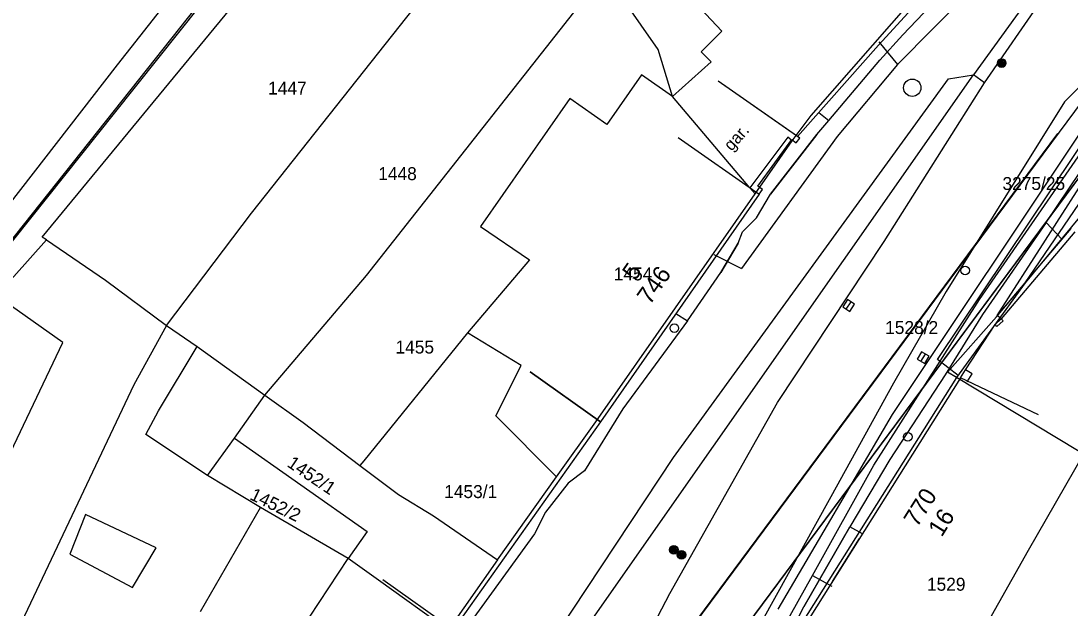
# Model space of a CAD drawing. Extents: x -601580 to 4, y -1204314 to 4.
# Drawn here: x -600374.2 to -600313.5, y -1203904.6 to -1203870.6 of the extents above; entities that cross this region are included whole.
import ezdxf

# ---------------------------------------------------------------- set-up
doc = ezdxf.new("R2010")
doc.units = 0
for name, color, linetype in [('00-INNOGY-NTL', 7, 'Continuous'), ('00-KN-HRANICE PARCEL', 7, 'Continuous'), ('00-KN-PARC. CISLA', 7, 'Continuous'), ('00-KN-VNITRNI KRESBA', 7, 'Continuous'), ('00-POLOHOPIS', 7, 'Continuous'), ('00-RAZÍTKO', 7, 'Continuous'), ('00-SITE KOM. KABEL', 7, 'Continuous'), ('00-VAK-KANAL-POTRUBI', 7, 'Continuous'), ('00-VAK-VODA-RAD IGIS', 7, 'Continuous'), ('Vrstva 25', 7, 'Continuous'), ('Vrstva 27', 7, 'Continuous'), ('Vrstva 28', 7, 'Continuous')]:
    doc.layers.add(name, color=color, linetype=linetype)

# ---------------------------------------------------------------- blocks, each defined once
blk = doc.blocks.new('6.01A_950')
at = {"layer": 'Vrstva 25'}
for radius in [0.25, 0.2, 0.15, 0.1, 0.05]:
    blk.add_circle((0, 0), radius, dxfattribs=at)
blk = doc.blocks.new('6.01A_952')
at = {"layer": 'Vrstva 25'}
for radius in [0.25, 0.2, 0.15, 0.1, 0.05]:
    blk.add_circle((0, 0), radius, dxfattribs=at)
blk = doc.blocks.new('6.30_40')
at = {"layer": 'Vrstva 27'}
blk.add_line((-0.25, 0.001), (0.25, -0.001), dxfattribs=at)
blk.add_lwpolyline([(-0.25, -0.25), (0.25, -0.25), (0.25, 0.25), (-0.25, 0.25)], close=True, dxfattribs=at)
blk = doc.blocks.new('6.30_42')
at = {"layer": 'Vrstva 27'}
blk.add_line((-0.25, 0), (0.25, 0), dxfattribs=at)
blk.add_lwpolyline([(-0.25, -0.25), (0.25, -0.25), (0.25, 0.25), (-0.25, 0.25)], close=True, dxfattribs=at)
blk = doc.blocks.new('6.14A_86')
at = {"layer": 'Vrstva 28'}
blk.add_circle((0, 0), 0.25, dxfattribs=at)
blk = doc.blocks.new('6.20_40')
at = {"layer": 'Vrstva 27'}
blk.add_circle((0, 0), 0.5, dxfattribs=at)
blk = doc.blocks.new('6.01A_954')
at = {"layer": 'Vrstva 25'}
for radius in [0.25, 0.2, 0.15, 0.1, 0.05]:
    blk.add_circle((0, 0), radius, dxfattribs=at)
blk = doc.blocks.new('6.14A_206')
at = {"layer": 'Vrstva 28'}
blk.add_circle((0, 0), 0.25, dxfattribs=at)
blk = doc.blocks.new('6.14A_302')
at = {"layer": 'Vrstva 28'}
blk.add_circle((0, 0), 0.25, dxfattribs=at)

msp = doc.modelspace()

# ---------------------------------------------------------------- linework, layer by layer
for points in [[(-600427.929, -1203789.586), (-600429.936, -1203788.096), (-600492.548, -1203872.448), (-600373.307, -1203960.957), (-600310.695, -1203876.605), (-600312.703, -1203875.115)], [(-600429.419, -1203791.594), (-600489.051, -1203871.931), (-600373.825, -1203957.46), (-600314.193, -1203877.122)]]:
    msp.add_lwpolyline(points)
at = {"layer": '00-INNOGY-NTL'}
for p, q in [((-600324.55, -1203871.82), (-600323.47, -1203873.13)), ((-600334.11, -1203884.13), (-600332.51, -1203884.94)), ((-600328.39, -1203902.68), (-600327.28, -1203903.3))]:
    msp.add_line(p, q, dxfattribs=at)
for points in [[(-600286.96, -1203840.01), (-600294.08, -1203835.84), (-600301.99, -1203847.39), (-600303.37, -1203849.38), (-600305.92, -1203853.05), (-600312.38, -1203861.49), (-600319.31, -1203868.9), (-600323.47, -1203873.13), (-600326.97, -1203877.3), (-600332.51, -1203884.94)], [(-600368.94, -1203988.96), (-600362.92, -1203979.22), (-600359.7, -1203973.75), (-600357.07, -1203969.3), (-600355.54, -1203966.01), (-600352.01, -1203958.39), (-600348.03, -1203948.55), (-600347.92, -1203948.26), (-600346.43, -1203944.25), (-600344.01, -1203937.76), (-600342.86, -1203934.56), (-600342.66, -1203934), (-600342.09, -1203933.68), (-600341.88, -1203933.03), (-600340.84, -1203929.9), (-600340, -1203927.34), (-600339.57, -1203926.28), (-600336.52, -1203918.66), (-600335.75, -1203916.73), (-600330.51, -1203906.49), (-600328.39, -1203902.68), (-600324.84, -1203896.3), (-600318.73, -1203886.72), (-600312.11, -1203877.17)]]:
    msp.add_lwpolyline(points, dxfattribs=at)
at = {"layer": '00-KN-HRANICE PARCEL'}
for p, q in [((-600316.1, -1203885.77), (-600311.15, -1203878.5)), ((-600310.54, -1203879.04), (-600316.1, -1203885.77)), ((-600340.93, -1203893.8), (-600331.72, -1203880.61)), ((-600375.63, -1203886.53), (-600372.72, -1203883.27)), ((-600316.1, -1203885.77), (-600320.07, -1203891.24)), ((-600365.77, -1203888.23), (-600364, -1203889.45)), ((-600364, -1203889.45), (-600360.08, -1203892.25)), ((-600320.07, -1203891.24), (-600320.59, -1203890.93)), ((-600320.07, -1203891.24), (-600328.99, -1203905.41)), ((-600361.85, -1203894.74), (-600360.08, -1203892.25)), ((-600343.2, -1203896.98), (-600340.93, -1203893.8)), ((-600354.58, -1203896.32), (-600352.35, -1203898.01)), ((-600346.62, -1203901.79), (-600343.2, -1203896.98)), ((-600358.06, -1203905.95), (-600355.26, -1203901.71)), ((-600353.5, -1203902.95), (-600355.26, -1203901.71)), ((-600346.62, -1203901.79), (-600349.48, -1203905.86)), ((-600349.48, -1203905.86), (-600353.5, -1203902.95))]:
    msp.add_line(p, q, dxfattribs=at)
for points in [[(-600372.72, -1203883.27), (-600372.97, -1203883.11), (-600353.88, -1203859.94)], [(-600365.77, -1203888.23), (-600360.85, -1203881.73), (-600344.95, -1203861.64)], [(-600331.72, -1203880.61), (-600329.57, -1203877.54), (-600328.48, -1203876.09), (-600317.9, -1203864.02)], [(-600360.08, -1203892.25), (-600354.2, -1203885.33), (-600340.41, -1203867.83)], [(-600336.5, -1203874.98), (-600337.33, -1203872.27), (-600340.41, -1203867.83)], [(-600377.01, -1203883.96), (-600368.61, -1203873.16), (-600365.53, -1203869.21)], [(-600336.5, -1203874.98), (-600338.29, -1203873.73), (-600340.29, -1203876.6), (-600342.44, -1203875.1), (-600347.61, -1203882.51), (-600344.78, -1203884.43), (-600348.35, -1203888.66)], [(-600331.72, -1203880.61), (-600332.02, -1203880.26), (-600336.5, -1203874.98)], [(-600372.72, -1203883.27), (-600369.3, -1203885.6), (-600365.77, -1203888.23)], [(-600320.59, -1203890.93), (-600317.76, -1203887.73), (-600316.1, -1203885.77)], [(-600365.77, -1203888.23), (-600367.67, -1203891.66), (-600375.01, -1203907.19), (-600380.53, -1203914.67)], [(-600348.35, -1203888.66), (-600354.36, -1203896.06), (-600354.58, -1203896.32)], [(-600343.2, -1203896.98), (-600346.72, -1203893.46), (-600345.25, -1203890.55), (-600348.35, -1203888.66)], [(-600299.4, -1203904.11), (-600300.3, -1203903.54), (-600304.84, -1203900.65), (-600312.69, -1203895.66), (-600313.06, -1203895.45), (-600320.07, -1203891.24)], [(-600360.08, -1203892.25), (-600357.86, -1203893.84), (-600354.58, -1203896.32)], [(-600355.26, -1203901.71), (-600360.34, -1203898.75), (-600363.4, -1203896.91), (-600361.85, -1203894.74)], [(-600361.85, -1203894.74), (-600354.16, -1203900.14), (-600355.26, -1203901.71)], [(-600352.35, -1203898.01), (-600350.32, -1203899.23), (-600346.62, -1203901.79)]]:
    msp.add_lwpolyline(points, dxfattribs=at)
at = {"layer": '00-KN-VNITRNI KRESBA'}
for p, q in [((-600333.65, -1203871.2), (-600336.14, -1203868.54)), ((-600334.83, -1203872.39), (-600333.65, -1203871.2)), ((-600334.26, -1203872.97), (-600334.83, -1203872.39)), ((-600336.5, -1203874.98), (-600334.26, -1203872.97)), ((-600329.83, -1203877.33), (-600332.02, -1203880.26)), ((-600329.57, -1203877.54), (-600329.83, -1203877.33)), ((-600371.77, -1203889.21), (-600375.2, -1203886.78)), ((-600378.81, -1203903.97), (-600371.77, -1203889.21)), ((-600366.24, -1203893.17), (-600364, -1203889.45)), ((-600366.98, -1203894.54), (-600366.24, -1203893.17)), ((-600363.4, -1203896.91), (-600366.98, -1203894.54)), ((-600315.89, -1203901.22), (-600312.69, -1203895.66)), ((-600363.8, -1203904.77), (-600360.34, -1203898.75)), ((-600370.46, -1203899.17), (-600371.37, -1203901.46)), ((-600366.37, -1203901.08), (-600370.46, -1203899.17)), ((-600371.37, -1203901.46), (-600367.74, -1203903.39)), ((-600367.74, -1203903.39), (-600366.37, -1203901.08)), ((-600319.61, -1203907.8), (-600315.89, -1203901.22))]:
    msp.add_line(p, q, dxfattribs=at)
at = {"layer": '00-POLOHOPIS'}
for p, q in [((-600318.438, -1203874.2), (-600293.21, -1203837.594)), ((-600310.591, -1203862.021), (-600319.085, -1203873.73)), ((-600344.023, -1203909.334), (-600319.085, -1203873.73)), ((-600336.441, -1203895.861), (-600320.535, -1203873.967)), ((-600320.535, -1203873.967), (-600319.085, -1203873.73)), ((-600318.438, -1203874.2), (-600319.085, -1203873.73)), ((-600324.257, -1203883.373), (-600318.438, -1203874.2)), ((-600323.768, -1203893.384), (-600312.785, -1203876.933)), ((-600317.704, -1203887.647), (-600311.559, -1203878.04)), ((-600313.443, -1203882.609), (-600317.704, -1203887.647)), ((-600313.214, -1203882.803), (-600317.475, -1203887.841)), ((-600330.417, -1203892.687), (-600324.257, -1203883.373)), ((-600317.832, -1203888.176), (-600317.475, -1203887.841)), ((-600317.729, -1203888.285), (-600317.372, -1203887.95)), ((-600317.475, -1203887.841), (-600317.704, -1203887.647)), ((-600317.372, -1203887.95), (-600317.475, -1203887.841)), ((-600319.542, -1203890.784), (-600317.832, -1203888.176)), ((-600317.729, -1203888.285), (-600317.832, -1203888.176)), ((-600319.831, -1203891.255), (-600319.542, -1203890.784)), ((-600319.158, -1203891.019), (-600319.542, -1203890.784)), ((-600319.447, -1203891.49), (-600319.158, -1203891.019)), ((-600336.653, -1203903.727), (-600330.417, -1203892.687)), ((-600330.376, -1203904.639), (-600323.768, -1203893.384)), ((-600356.068, -1203925.496), (-600336.441, -1203895.861)), ((-600327.238, -1203903.038), (-600325.668, -1203900.54)), ((-600340.383, -1203910.895), (-600336.653, -1203903.727))]:
    msp.add_line(p, q, dxfattribs=at)
for points in [[(-600321.298, -1203861.018), (-600317.583, -1203864.365), (-600320.205, -1203867.275), (-600320.946, -1203868.051), (-600324.579, -1203872.007), (-600329.269, -1203877.287), (-600333.854, -1203874.094)], [(-600336.16, -1203877.362), (-600331.479, -1203880.625), (-600331.285, -1203880.358), (-600331.552, -1203880.164), (-600329.6, -1203877.475), (-600329.333, -1203877.669), (-600329.127, -1203877.386), (-600333.854, -1203874.094)], [(-600336.16, -1203877.362), (-600331.479, -1203880.625), (-600340.658, -1203893.793), (-600344.737, -1203890.902)], [(-600344.737, -1203890.902), (-600340.658, -1203893.793), (-600349.186, -1203905.824), (-600353.265, -1203902.932)], [(-600315.317, -1203893.405), (-600319.831, -1203891.255), (-600328.915, -1203905.705), (-600328.915, -1203905.705), (-600321.108, -1203910.236)]]:
    msp.add_lwpolyline(points, dxfattribs=at)
at = {"layer": '00-RAZÍTKO'}
for points in [[(-600492.548, -1203872.448), (-600304.712, -1203619.391), (-600185.471, -1203707.9), (-600373.307, -1203960.957)], [(-600489.051, -1203871.931), (-600304.195, -1203622.889), (-600188.969, -1203708.417), (-600373.825, -1203957.46)]]:
    msp.add_lwpolyline(points, close=True, dxfattribs=at)
at = {"layer": '00-SITE KOM. KABEL'}
for points in [[(-600319.96, -1203891.12), (-600321.17, -1203890.19), (-600304.06, -1203864.65), (-600294.17, -1203850.07), (-600282.45, -1203832.63), (-600279.97, -1203828.88), (-600279.74, -1203826.75), (-600273.69, -1203817.55), (-600271.37, -1203815.37), (-600264.47, -1203805.03), (-600246.59, -1203780.19), (-600235.23, -1203765.23)], [(-600327.45, -1203876.37), (-600324.5, -1203872.88), (-600323.17, -1203871.41), (-600320.76, -1203868.88), (-600319.59, -1203867.6)], [(-600314.88, -1203882.27), (-600311.58, -1203877.37), (-600309.4, -1203874.07), (-600308.67, -1203873.05), (-600307.1, -1203870.76)], [(-600323.17, -1203871.41), (-600324.5, -1203872.88)], [(-600328.03, -1203875.9), (-600327.45, -1203876.37)], [(-600335.63, -1203887.95), (-600333.7, -1203885.16), (-600332.69, -1203883.46), (-600332.45, -1203882.82), (-600331.63, -1203882), (-600330.82, -1203880.63), (-600328.15, -1203877.19), (-600327.45, -1203876.37)], [(-600328.15, -1203877.19), (-600330.82, -1203880.63)], [(-600314.88, -1203882.27), (-600318.56, -1203887.59), (-600320.72, -1203891.09), (-600323.93, -1203895.97), (-600326.24, -1203899.88)], [(-600313.97, -1203883.24), (-600314.88, -1203882.27)], [(-600332.69, -1203883.46), (-600333.7, -1203885.16)], [(-600336.31, -1203887.53), (-600335.63, -1203887.95)], [(-600335.63, -1203887.95), (-600339.37, -1203893.05), (-600341.59, -1203896.64), (-600342.53, -1203897.34), (-600343.84, -1203899.03), (-600344.48, -1203900.27), (-600348.64, -1203906.02), (-600350.48, -1203909.08), (-600353.75, -1203915.34)], [(-600318.56, -1203887.59), (-600320.72, -1203891.09)], [(-600339.37, -1203893.05), (-600341.59, -1203896.64)], [(-600335.36, -1203917.21), (-600332.58, -1203911.67), (-600328.89, -1203904.5), (-600328.02, -1203902.96), (-600326.24, -1203899.88)], [(-600326.24, -1203899.88), (-600328.02, -1203902.96)], [(-600325.5, -1203900.27), (-600326.24, -1203899.88)], [(-600328.02, -1203902.96), (-600328.89, -1203904.5)]]:
    msp.add_lwpolyline(points, dxfattribs=at)
at = {"layer": '00-VAK-KANAL-POTRUBI'}
for points in [[(-600326.016, -1203831.688), (-600331.317, -1203836.686), (-600343.362, -1203848.044), (-600352.098, -1203856.282), (-600362.567, -1203868.11), (-600368.81, -1203875.94), (-600393.327, -1203906.691), (-600394.486, -1203908.145)], [(-600333.782, -1203838.946), (-600352.131, -1203856.227), (-600362.652, -1203868.025), (-600394.483, -1203908.108), (-600394.486, -1203908.145)]]:
    msp.add_lwpolyline(points, dxfattribs=at)
at = {"layer": '00-VAK-VODA-RAD IGIS'}
msp.add_lwpolyline([(-600276.695, -1203819.684), (-600279.39, -1203823.44), (-600280.72, -1203826.32), (-600281.68, -1203827.91), (-600293.34, -1203845.51), (-600302.48, -1203859.3), (-600311.62, -1203873.1), (-600313.81, -1203875.29), (-600320.66, -1203886.26), (-600323.71, -1203891.56), (-600327.34, -1203898.14), (-600331.383, -1203905.452), (-600338.1, -1203917.89), (-600346.75, -1203940.93), (-600353.201, -1203956.994), (-600355.466, -1203962.632), (-600360.94, -1203972.29), (-600370.25, -1203987.62), (-600375.59, -1203995.85), (-600378.929, -1203999.479), (-600379.29, -1204000.12)], dxfattribs=at)

# ---------------------------------------------------------------- block references
at = {"layer": '00-POLOHOPIS'}
for name, p, xscale, yscale, rotation in [('6.01A_954', (-600317.451, -1203873.048), 0.99999916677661, 0.99999916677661, 59.52314605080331), ('6.20_40', (-600322.624, -1203874.474), 0.99999916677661, 0.99999916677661, 59.52314605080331), ('6.14A_302', (-600319.561, -1203885.053), 1.00000010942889, 1.0000001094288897, 147.91820085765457), ('6.30_40', (-600326.304, -1203887.077), 1.00000166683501, 1.0000016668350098, 56.90111451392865), ('6.30_42', (-600321.994, -1203890.093), 0.99999916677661, 0.99999916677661, 59.52314605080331), ('6.14A_86', (-600322.889, -1203894.665), 0.99999916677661, 0.99999916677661, 59.52314605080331)]:
    msp.add_blockref(name, p, dxfattribs=dict(at, xscale=xscale, yscale=yscale, rotation=rotation))
at = {"layer": '00-POLOHOPIS', "rotation": -90.00000000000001}
for name, p in [('6.14A_206', (-600336.392, -1203888.38)), ('6.01A_952', (-600336.416, -1203901.209)), ('6.01A_950', (-600335.981, -1203901.488))]:
    msp.add_blockref(name, p, dxfattribs=at)

# ---------------------------------------------------------------- texts
at = {"layer": '00-KN-PARC. CISLA'}
for s, p in [('1447', (-600359.895, -1203874.87)), ('1448', (-600353.525, -1203879.82)), ('3275/25', (-600317.405, -1203880.39)), ('1454', (-600339.895, -1203885.62)), ('1528/2', (-600324.193, -1203888.72)), ('1455', (-600352.525, -1203889.85)), ('1453/1', (-600349.709, -1203898.21)), ('1529', (-600321.775, -1203903.57))]:
    msp.add_text(s, height=0.75, dxfattribs=at).set_placement(p)
for s, rotation, p in [('1452/1', 326, (-600358.853, -1203896.348)), ('1452/2', 334, (-600361.005, -1203898.261))]:
    msp.add_text(s, height=0.75, rotation=rotation, dxfattribs=at).set_placement(p)
at = {"layer": '00-POLOHOPIS'}
for s, height, rotation, p in [('gar.', 0.7, 48.34021, (-600333.078, -1203878.179)), ('5', 1, 55.12086, (-600338.657, -1203885.677)), ('746', 1, 55.12086, (-600337.808, -1203887.081)), ('770', 1, 57.84446, (-600322.342, -1203899.946)), ('16', 1, 57.84446, (-600320.922, -1203900.505))]:
    msp.add_text(s, height=height, rotation=rotation, dxfattribs=at).set_placement(p)

doc.saveas('drawing.dxf')
